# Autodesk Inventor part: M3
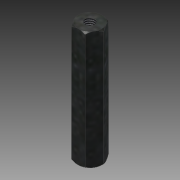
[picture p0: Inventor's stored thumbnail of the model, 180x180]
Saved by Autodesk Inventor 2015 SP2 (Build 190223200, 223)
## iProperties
Created: 2012-08
Part Number: M3
Material: Stahl
Document SubType Name: Modeling
Designer: rYan
Mass: 3.36246 g
Surface Area: 5.74911 cm^2
Volume: 0.428339 cm^3
Density: 7.85 g/cm^3
Appearance: Platte
Author: rYan
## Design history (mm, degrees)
derived "Abstandsbolzen Typ A.ipt"
feature "Volumenkörper1::Abstandsbolzen Typ A.ipt"
tag "Bezeichnung1"
node "Volumenkörper1"
other parameters: "SW" = 6, "d2" = 0, "d16" = 45 deg
